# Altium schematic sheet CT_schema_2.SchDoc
size 379 x 228 mm
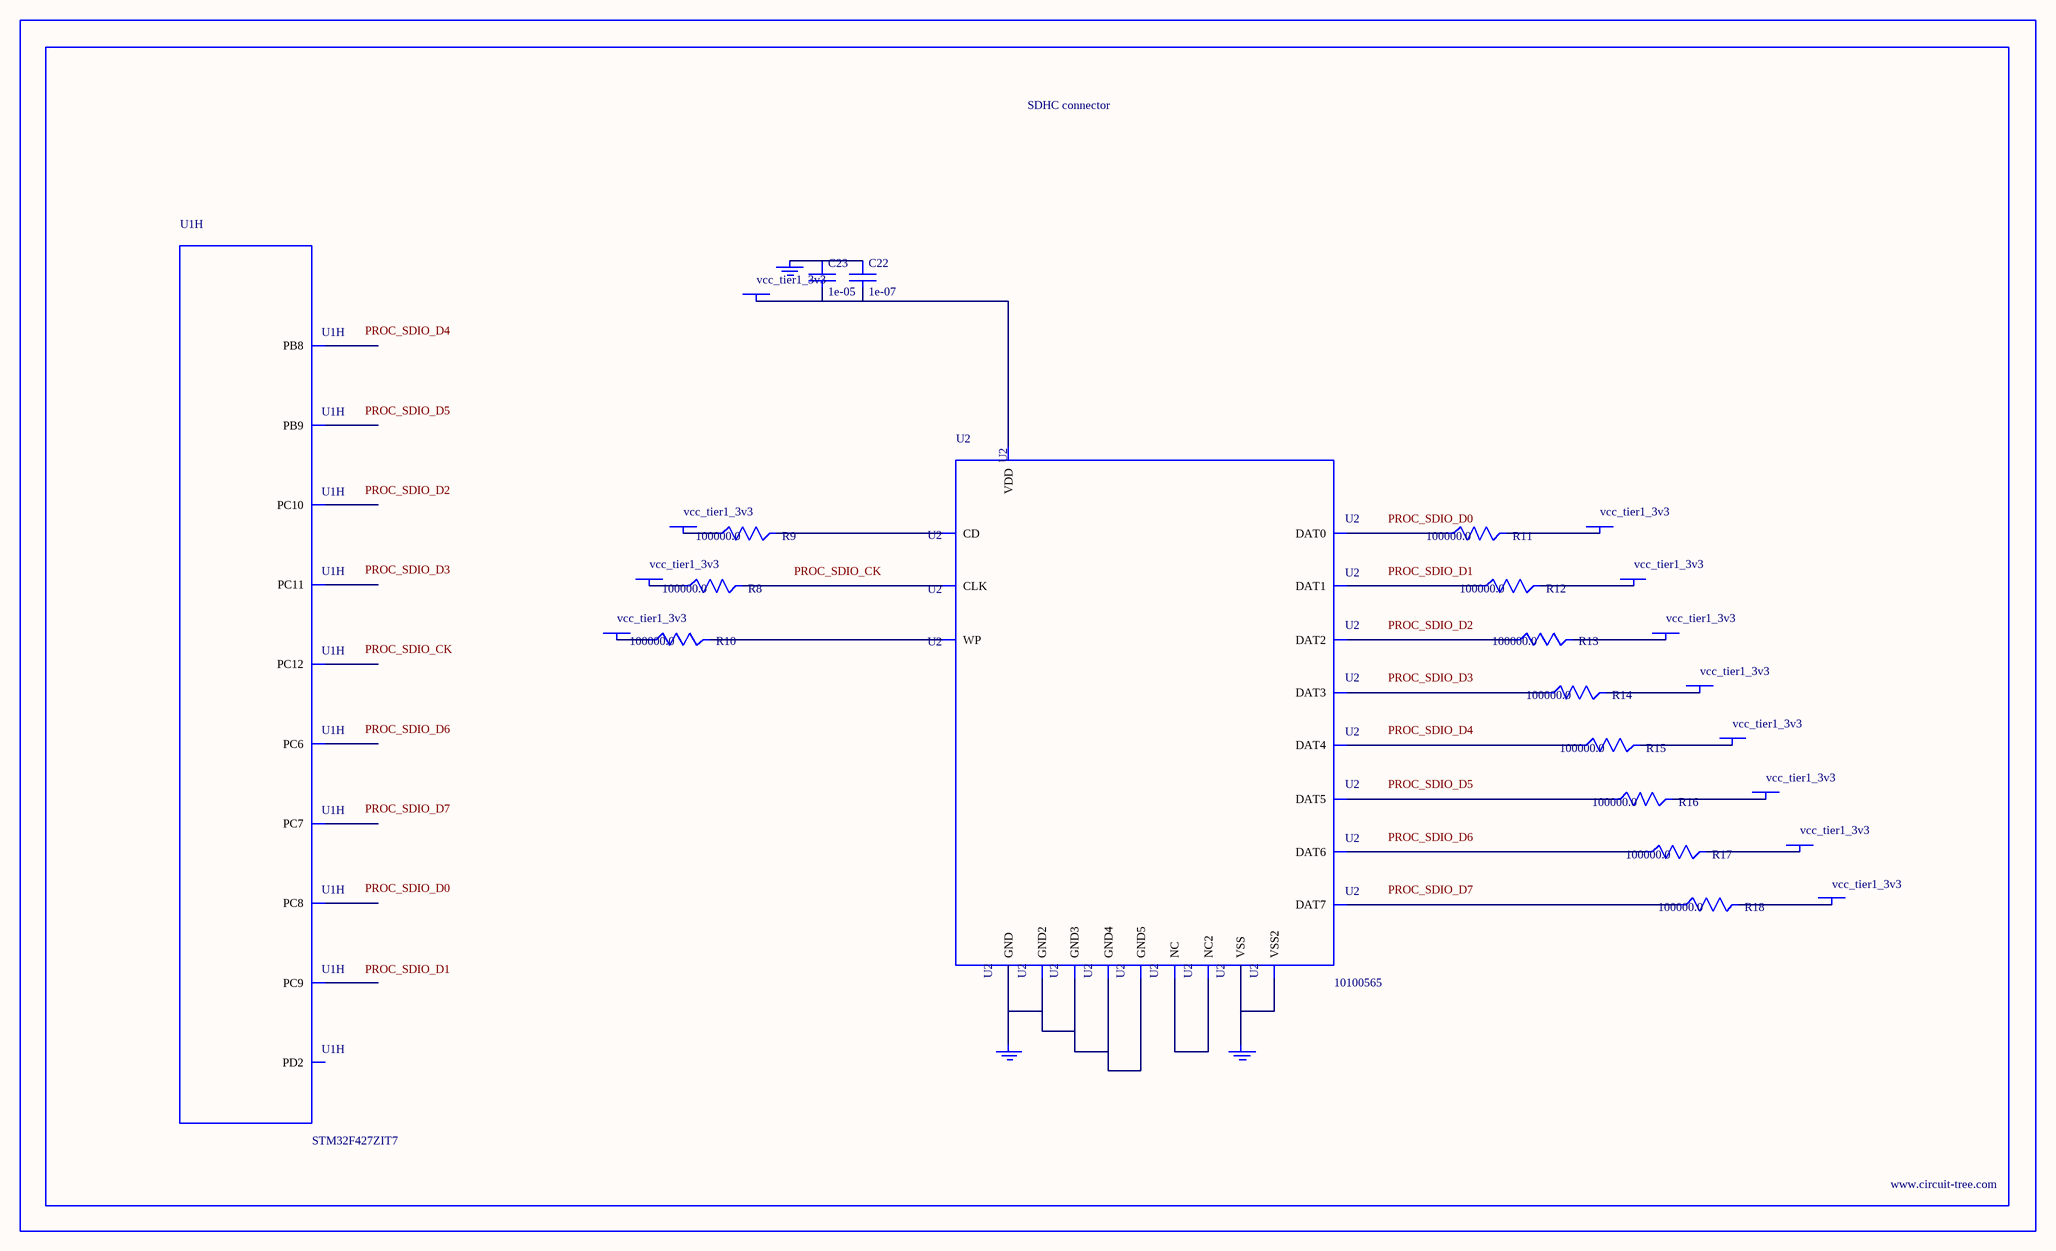
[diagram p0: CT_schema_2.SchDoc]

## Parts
BORDER1  (no value)
C22  1e-07  [C0402]
C23  1e-05  [C0805]
GND_INSTANCE_1_0  (no value)
GND_INSTANCE_1_1  (no value)
GND_INSTANCE_1_2  (no value)
POWER_INSTANCE_1_0  vcc_tier1_3v3
POWER_INSTANCE_1_1  vcc_tier1_3v3
POWER_INSTANCE_1_2  vcc_tier1_3v3
POWER_INSTANCE_1_3  vcc_tier1_3v3
POWER_INSTANCE_1_4  vcc_tier1_3v3
POWER_INSTANCE_1_5  vcc_tier1_3v3
POWER_INSTANCE_1_6  vcc_tier1_3v3
POWER_INSTANCE_1_7  vcc_tier1_3v3
POWER_INSTANCE_1_8  vcc_tier1_3v3
POWER_INSTANCE_1_9  vcc_tier1_3v3
POWER_INSTANCE_1_10  vcc_tier1_3v3
POWER_INSTANCE_1_11  vcc_tier1_3v3
R8  100000.0  [R0603]
R9  100000.0  [R0603]
R10  100000.0  [R0603]
R11  100000.0  [R0603]
R12  100000.0  [R0603]
R13  100000.0  [R0603]
R14  100000.0  [R0603]
R15  100000.0  [R0603]
R16  100000.0  [R0603]
R17  100000.0  [R0603]
R18  100000.0  [R0603]
U1  STM32F427ZIT7  [LQFP144]  (part H of 13)
U2  10100565  [10100565]

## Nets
NetC22_1: C22.1 C23.1 GND_INSTANCE_1_0.0(GND)
NetC22_2: C22.2 C23.2 POWER_INSTANCE_1_7.0(PWR) U2.9(VDD)
NetGND_INSTANCE_1_1_0: GND_INSTANCE_1_1.0(GND) U2.6(VSS) U2.10(VSS2)
NetGND_INSTANCE_1_2_0: GND_INSTANCE_1_2.0(GND) U2.12(GND) U2.16(GND2) U2.17(GND3) U2.20(GND4) U2.21(GND5)
NetPOWER_INSTANCE_1_0_0: POWER_INSTANCE_1_0.0(PWR) R10.1
NetPOWER_INSTANCE_1_1_0: POWER_INSTANCE_1_1.0(PWR) R9.1
NetPOWER_INSTANCE_1_2_0: POWER_INSTANCE_1_2.0(PWR) R12.2
NetPOWER_INSTANCE_1_3_0: POWER_INSTANCE_1_3.0(PWR) R11.2
NetPOWER_INSTANCE_1_4_0: POWER_INSTANCE_1_4.0(PWR) R18.2
NetPOWER_INSTANCE_1_5_0: POWER_INSTANCE_1_5.0(PWR) R17.2
NetPOWER_INSTANCE_1_6_0: POWER_INSTANCE_1_6.0(PWR) R8.1
NetPOWER_INSTANCE_1_8_0: POWER_INSTANCE_1_8.0(PWR) R16.2
NetPOWER_INSTANCE_1_9_0: POWER_INSTANCE_1_9.0(PWR) R15.2
NetPOWER_INSTANCE_1_10_0: POWER_INSTANCE_1_10.0(PWR) R14.2
NetPOWER_INSTANCE_1_11_0: POWER_INSTANCE_1_11.0(PWR) R13.2
NetR8_2: R8.2 U2.8(CLK)
NetR9_2: R9.2 U2.2(CD)
NetR10_2: R10.2 U2.1(WP)
NetR11_1: R11.1 U2.4(DAT0)
NetR12_1: R12.1 U2.3(DAT1)
NetR13_1: R13.1 U2.15(DAT2)
NetR14_1: R14.1 U2.14(DAT3)
NetR15_1: R15.1 U2.13(DAT4)
NetR16_1: R16.1 U2.11(DAT5)
NetR17_1: R17.1 U2.7(DAT6)
NetR18_1: R18.1 U2.5(DAT7)
NetU2_18: U2.18(NC) U2.19(NC2)

Not connected (* = marked no-connect by the designer): U1 96(PC6) 97(PC7) 98(PC8) 99(PC9) 111(PC10) 112(PC11) 113(PC12) 116(PD2) 139(PB8) 140(PB9)

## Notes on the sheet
- Labels drawn without touching a wire or pin: PROC_SDIO_CK, PROC_SDIO_D0, PROC_SDIO_D1, PROC_SDIO_D2, PROC_SDIO_D3, PROC_SDIO_D4, PROC_SDIO_D5, PROC_SDIO_D6, PROC_SDIO_D7

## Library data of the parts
BORDER1 = BORDER_PAGE1
C22 = C0402C104K3RACTU
C23 = C0805C106K8RACTU
GND_INSTANCE_1_0-GND_INSTANCE_1_2 = GND
POWER_INSTANCE_1_0-POWER_INSTANCE_1_11 = PWR
R8-R18 = RC0603JR-07100KL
